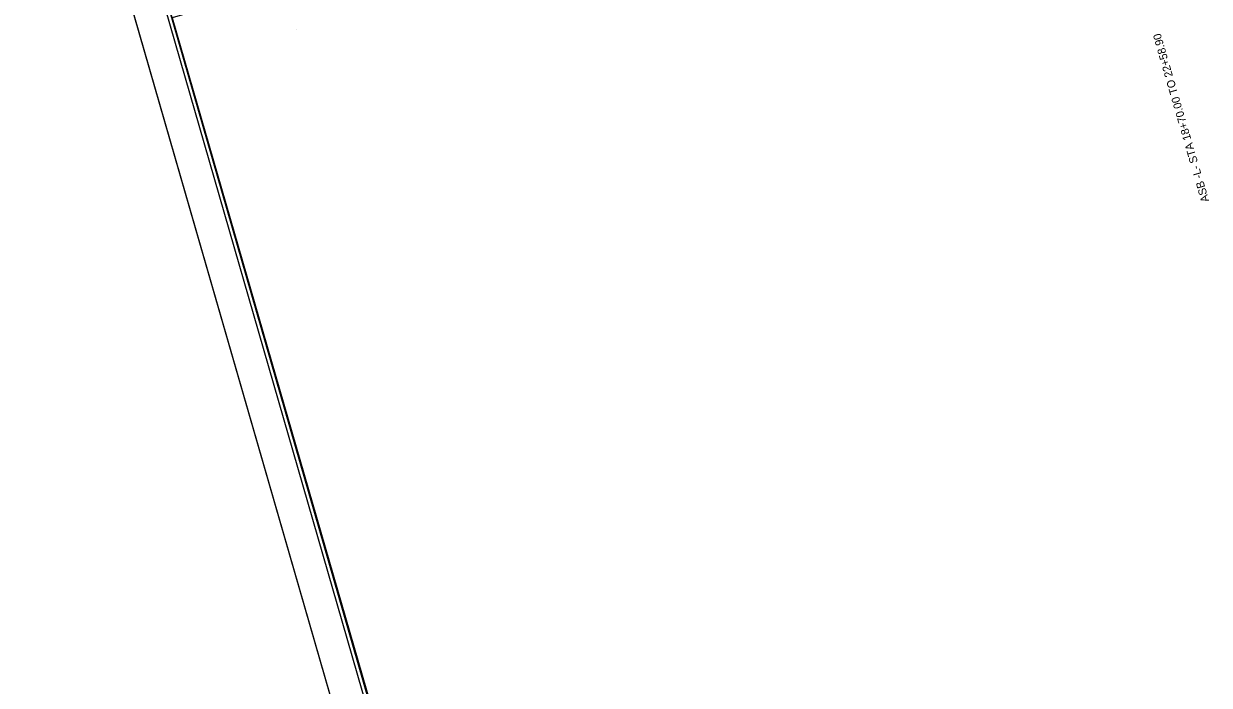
# Model space of a CAD drawing. Extents: x 2167139 to 2168658, y 842502 to 844423.
# Drawn here: x 2167139 to 2167880, y 843463 to 843876 of the extents above; entities that cross this region are included whole.
import ezdxf

# ---------------------------------------------------------------- set-up
doc = ezdxf.new("R2010")
doc.units = 0
for name, color, linetype in [('Prop Dimension Text', 7, 'Continuous'), ('Sheet Clip Boundary CELL', 7, 'Continuous'), ('Sheet Cutting Line CELL', 7, 'Continuous'), ('Sheet Layout Plan Border', 7, 'Continuous'), ('Sheet North Arrow Point CELL', 7, 'Continuous'), ('Sheet Plan CELL', 7, 'Continuous'), ('Sheet Plan Layout CELL', 7, 'Continuous'), ('Sheet Plot Border Inside CELL', 7, 'Continuous'), ('Sheet Plot Border Outside CELL', 7, 'Continuous')]:
    doc.layers.add(name, color=color, linetype=linetype)

msp = doc.modelspace()

# ---------------------------------------------------------------- linework, layer by layer
at = {"layer": 'Sheet Clip Boundary CELL'}
msp.add_lwpolyline([(2168333.42, 842899.61), (2168359.34, 842906.72), (2168266.95, 843188.11), (2168382.06, 843220.66), (2168502.28, 843263.66), (2168187.91, 844352.53), (2167382.3, 844119.94), (2167434.8, 843938.11), (2167231.61, 843879.44), (2167577.57, 842681.16)], close=True, dxfattribs=at)
at = {"layer": 'Sheet Cutting Line CELL'}
msp.add_line((2167138.92, 844119.41), (2167605.9, 842501.98), dxfattribs=at)
at = {"layer": 'Sheet Layout Plan Border'}
msp.add_lwpolyline([(2168586.35, 842975.21), (2168177.55, 844388.42), (2167371.94, 844155.82), (2167434.8, 843938.11), (2167231.61, 843879.44), (2167577.55, 842683.96)], close=True, dxfattribs=at)
at = {"layer": 'Sheet North Arrow Point CELL'}
msp.add_line((2167309.69, 843871.95), (2167309.69, 843871.95), dxfattribs=at)
at = {"layer": 'Sheet Plan CELL'}
for points in [[(2167165.23, 844109.34), (2167581.32, 842668.17), (2168590.12, 842959.42), (2168174.04, 844400.57)], [(2168590.12, 842959.42), (2167581.35, 842668.15), (2167220.72, 843917.11), (2167364.89, 843958.75), (2167309.41, 844150.94), (2168174.04, 844400.57)]]:
    msp.add_lwpolyline(points, close=True, dxfattribs=at)
at = {"layer": 'Sheet Plan Layout CELL'}
msp.add_lwpolyline([(2167581.35, 842668.15), (2168590.12, 842959.42), (2168174.04, 844400.56), (2167368.43, 844167.97), (2167434.8, 843938.11), (2167231.61, 843879.44)], close=True, dxfattribs=at)
at = {"layer": 'Sheet Plot Border Inside CELL'}
msp.add_lwpolyline([(2168635.11, 842812.65), (2168172.98, 844413.26), (2167159.38, 844120.64), (2167621.51, 842520.01)], close=True, dxfattribs=at)
at = {"layer": 'Sheet Plot Border Outside CELL'}
msp.add_lwpolyline([(2168657.93, 842805.71), (2168190.95, 844423.15), (2167138.92, 844119.41), (2167605.9, 842501.98)], close=True, dxfattribs=at)

# ---------------------------------------------------------------- texts
at = {"layer": 'Prop Dimension Text'}
msp.add_text('ASB -L- STA 18+70.00 TO 22+58.90', height=5, rotation=106.18713, dxfattribs=at).set_placement((2167879.85, 843765.09))

doc.saveas('drawing.dxf')
